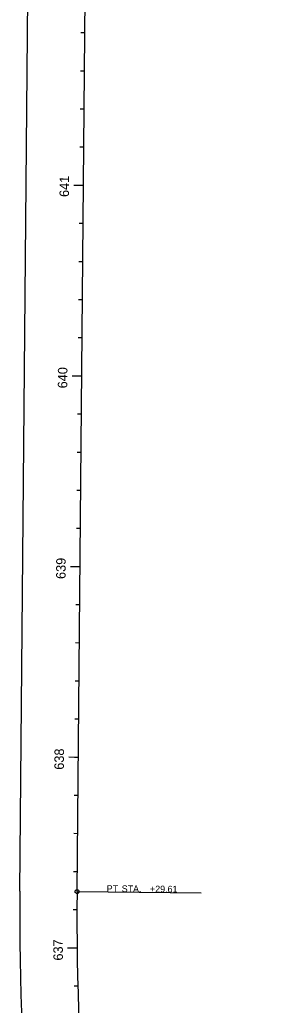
# Model space of a CAD drawing. Extents: x 2003883 to 2007688, y 399149 to 412300.
# Drawn here: x 2003910 to 2004044, y 410749 to 411266 of the extents above; entities that cross this region are included whole.
import ezdxf

# ---------------------------------------------------------------- set-up
doc = ezdxf.new("R2010")
doc.units = 0
for name, color, linetype in [('BaselineSurvey', 7, 'Continuous'), ('DataBoxWt2', 7, 'Continuous'), ('Default', 7, 'Continuous'), ('EaseLine_ep', 7, 'Continuous'), ('PropertyLine_ep', 7, 'Continuous'), ('PropertyLineHook_ep', 7, 'Continuous'), ('PropertyLineSymbol_ep', 7, 'Continuous'), ('SubDivLineText', 7, 'Continuous'), ('SubLotNumberText', 7, 'Continuous'), ('SubVacOrigLotStaTie', 7, 'Continuous'), ('TextMisc', 7, 'Continuous')]:
    doc.layers.add(name, color=color, linetype=linetype)

msp = doc.modelspace()

# ---------------------------------------------------------------- linework, layer by layer
at = {"layer": 'DataBoxWt2'}
for p, q in [((2003942.15, 411078.98), (2003937.15, 411079.03)), ((2003940.36, 410878.99), (2003938.36, 410879.01))]:
    msp.add_line(p, q, dxfattribs=at)
at = {"layer": 'Default'}
msp.add_line((2003939.73, 410808.61), (2003953.03, 412299.6), dxfattribs=at)
msp.add_arc((2005402.52, 410795.56), 1462.84, 179.48905, 201.72713, dxfattribs=at)
at = {"layer": 'EaseLine_ep'}
msp.add_line((2003909.74, 410808.88), (2003923.03, 412299.87), dxfattribs=at)
msp.add_arc((2005402.52, 410795.56), 1492.84, 179.48905, 201.72713, dxfattribs=at)
at = {"layer": 'PropertyLine_ep'}
msp.add_line((2003939.73, 410808.61), (2003953.03, 412299.6), dxfattribs=at)
msp.add_arc((2005402.52, 410795.56), 1462.84, 179.48905, 201.72713, dxfattribs=at)
at = {"layer": 'PropertyLineHook_ep'}
for p, q in [((2003943.75, 411258.98), (2003941.75, 411258.99)), ((2003943.57, 411238.98), (2003941.57, 411238.99)), ((2003943.39, 411218.98), (2003941.39, 411218.99)), ((2003943.22, 411198.98), (2003941.22, 411199)), ((2003943.04, 411178.98), (2003938.04, 411179.02)), ((2003942.86, 411158.98), (2003940.86, 411159)), ((2003942.68, 411138.98), (2003940.68, 411139)), ((2003942.5, 411118.98), (2003940.5, 411119)), ((2003942.32, 411098.98), (2003940.32, 411099)), ((2003942.15, 411078.98), (2003937.15, 411079.03)), ((2003941.97, 411058.98), (2003939.97, 411059)), ((2003941.79, 411038.98), (2003939.79, 411039)), ((2003941.61, 411018.98), (2003939.61, 411019)), ((2003941.43, 410998.99), (2003939.43, 410999)), ((2003941.25, 410978.99), (2003936.25, 410979.03)), ((2003941.08, 410958.99), (2003939.08, 410959)), ((2003940.9, 410938.99), (2003938.9, 410939.01)), ((2003940.72, 410918.99), (2003938.72, 410919.01)), ((2003940.54, 410898.99), (2003938.54, 410899.01)), ((2003940.36, 410878.99), (2003935.36, 410879.03)), ((2003940.18, 410858.99), (2003938.18, 410859.01)), ((2003940.01, 410838.99), (2003938.01, 410839.01)), ((2003939.83, 410818.99), (2003937.83, 410819.01)), ((2003939.68, 410798.99), (2003937.68, 410799)), ((2003939.77, 410778.99), (2003934.77, 410778.94)), ((2003940.13, 410759), (2003938.13, 410758.95))]:
    msp.add_line(p, q, dxfattribs=at)
at = {"layer": 'SubDivLineText'}
for p, q in [((2003943.04, 411178.98), (2003941.04, 411179)), ((2003942.15, 411078.98), (2003937.15, 411079.03)), ((2003941.25, 410978.99), (2003939.25, 410979)), ((2003940.36, 410878.99), (2003938.36, 410879.01)), ((2003939.77, 410778.99), (2003937.77, 410778.97))]:
    msp.add_line(p, q, dxfattribs=at)
at = {"layer": 'SubVacOrigLotStaTie'}
msp.add_line((2003942.15, 411078.98), (2003940.15, 411079), dxfattribs=at)
at = {"layer": 'TextMisc'}
msp.add_line((2003939.73, 410808.61), (2004004.73, 410808.03), dxfattribs=at)
msp.add_circle((2003939.73, 410808.61), 1, dxfattribs=at)

# ---------------------------------------------------------------- texts
at = {"layer": 'BaselineSurvey'}
msp.add_text('640', height=4.98, rotation=89.489, dxfattribs=at).set_placement((2003934.59, 411072.55))
at = {"layer": 'PropertyLineSymbol_ep'}
for s, rotation, p in [('641', 89.489, (2003935.48, 411172.93)), ('640', 89.489, (2003934.59, 411072.55)), ('639', 89.489, (2003933.7, 410972.55)), ('638', 89.489, (2003932.8, 410872.51)), ('637', 90.649, (2003932.34, 410772.46))]:
    msp.add_text(s, height=4.98, rotation=rotation, dxfattribs=at).set_placement(p)
at = {"layer": 'SubLotNumberText'}
msp.add_text('640', height=4.98, rotation=89.489, dxfattribs=at).set_placement((2003934.59, 411072.55))
at = {"layer": 'TextMisc'}
for s, p in [('PT', (2003955.25, 410808.47)), (' STA. ', (2003961.83, 410808.41)), ('+29.61', (2003977.96, 410808.27))]:
    msp.add_text(s, height=3.48, rotation=359.489, dxfattribs=at).set_placement(p)

doc.saveas('drawing.dxf')
